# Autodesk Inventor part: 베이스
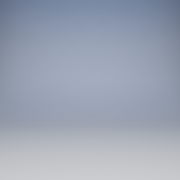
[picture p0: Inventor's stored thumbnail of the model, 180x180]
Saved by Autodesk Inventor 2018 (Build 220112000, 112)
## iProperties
Created: 2020-05
Part Number: 베이스
Material: Generic
Document SubType Name: Modeling
Designer: theplan76
Density: 1 g/cm^3
Appearance: Default
Author: theplan76
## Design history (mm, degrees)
